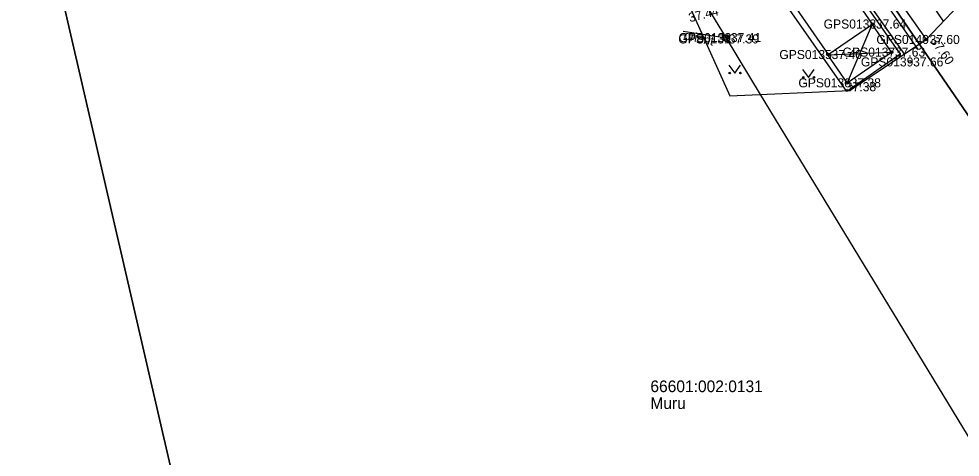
# Model space of a CAD drawing. Extents: x 626224 to 628280, y 6467750 to 6471135.
# Drawn here: x 627647 to 627719.8, y 6468553.4 to 6468587.3 of the extents above; entities that cross this region are included whole.
import ezdxf

# ---------------------------------------------------------------- set-up
doc = ezdxf.new("R2010")
doc.units = 0
for name, color, linetype in [('HALJASTUS', 7, 'Continuous'), ('HOONE', 7, 'Continuous'), ('HOONEDET', 7, 'Continuous'), ('KORGUS-EH2000', 7, 'Continuous'), ('MOOTKORG-EH2000', 7, 'Continuous'), ('MOOTMPUNKT', 7, 'Continuous'), ('MOOTNR', 7, 'Continuous'), ('MOOTPIIR', 7, 'Continuous'), ('MPKAABEL', 7, 'Continuous'), ('MPOHULIIN', 7, 'Continuous'), ('Muu rajatis Katusealune', 7, 'Continuous'), ('PIIR', 7, 'Continuous'), ('POST', 7, 'Continuous'), ('SITRASS', 7, 'Continuous')]:
    doc.layers.add(name, color=color, linetype=linetype)

msp = doc.modelspace()

# ---------------------------------------------------------------- linework, layer by layer
at = {"layer": 'HALJASTUS'}
for p, q in [((627701.907, 6468583.694), (627702.37, 6468583.087)), ((627702.37, 6468583.087), (627702.816, 6468583.694)), ((627707.596, 6468583.357), (627708.06, 6468582.75)), ((627708.06, 6468582.75), (627708.505, 6468583.357))]:
    msp.add_line(p, q, dxfattribs=at)
for points in [[(627673.61, 6468619.969), (627672.976, 6468621.286), (627679.187, 6468622.456), (627687.969, 6468624.157), (627689.948, 6468620.551), (627692.796, 6468621.064), (627698.292, 6468613.159), (627705.989, 6468601.538), (627717.166, 6468585.678)], [(627716.572, 6468584.873), (627705.028, 6468601.396), (627692.406, 6468620.356), (627689.621, 6468619.759), (627687.703, 6468623.543), (627673.321, 6468620.739)], [(627673.61, 6468619.969), (627679.701, 6468621.092), (627687.315, 6468622.642), (627689.297, 6468618.889), (627691.61, 6468619.392), (627696.609, 6468612.017), (627704.309, 6468600.39), (627715.503, 6468584.506)]]:
    msp.add_lwpolyline(points, dxfattribs=at)
for centre in [(627701.969, 6468583.087), (627702.798, 6468583.087), (627707.659, 6468582.75), (627708.488, 6468582.75)]:
    msp.add_circle(centre, 0.055, dxfattribs=at)
at = {"layer": 'HOONE'}
for p, q in [((627714.488, 6468584.702), (627713.001, 6468586.862)), ((627711.065, 6468582.328), (627709.57, 6468584.502)), ((627711.065, 6468582.328), (627714.488, 6468584.702))]:
    msp.add_line(p, q, dxfattribs=at)
msp.add_lwpolyline([(627706.037, 6468589.677), (627709.589, 6468584.515), (627713.017, 6468586.873), (627709.466, 6468592.035)], close=True, dxfattribs=at)
at = {"layer": 'HOONEDET'}
for p, q in [((627713.001, 6468586.862), (627711.065, 6468582.328)), ((627709.57, 6468584.502), (627714.488, 6468584.702))]:
    msp.add_line(p, q, dxfattribs=at)
at = {"layer": 'KORGUS-EH2000'}
for centre in [(627701.799, 6468585.823), (627717.166, 6468585.678), (627711.065, 6468582.328)]:
    msp.add_circle(centre, 0.1, dxfattribs=at)
at = {"layer": 'MOOTMPUNKT'}
for centre in [(627713.017, 6468586.873), (627701.634, 6468585.72), (627701.799, 6468585.823), (627717.166, 6468585.678), (627714.488, 6468584.702), (627709.588, 6468584.515), (627715.897, 6468583.946), (627711.065, 6468582.328)]:
    msp.add_circle(centre, 0.1, dxfattribs=at)
at = {"layer": 'MOOTPIIR'}
msp.add_lwpolyline([(627644.92, 6468614.927), (627687.389, 6468622.904), (627689.377, 6468619.311), (627692.038, 6468619.76), (627702.956, 6468602.021), (627695.606, 6468595.477), (627701.992, 6468581.333), (627711.232, 6468581.738), (627717.166, 6468585.678), (627720.646, 6468589.364)], dxfattribs=at)
at = {"layer": 'MPKAABEL'}
msp.add_line((627701.716, 6468585.772), (627698.369, 6468586.307), dxfattribs=at)
at = {"layer": 'MPOHULIIN'}
for points in [[(627704.355, 6468581.436), (627701.716, 6468585.772), (627695.728, 6468595.585)], [(627776.772, 6468462.547), (627753.896, 6468500.245), (627726.889, 6468544.419), (627704.355, 6468581.436)]]:
    msp.add_lwpolyline(points, dxfattribs=at)
at = {"layer": 'Muu rajatis Katusealune'}
msp.add_lwpolyline([(627705.521, 6468589.562), (627709.645, 6468592.435), (627715.151, 6468584.531), (627711.028, 6468581.659)], close=True, dxfattribs=at)
at = {"layer": 'PIIR'}
msp.add_lwpolyline([(627746.91, 6468541.23), (627688.18, 6468626.77), (627684.35, 6468632.16), (627686.69, 6468632.75), (627663.66, 6468662.2), (627667.34, 6468664.86), (627649.05, 6468692.73), (627646.31, 6468691.19), (627629.12, 6468721.76), (627618.92, 6468715.04), (627606.91, 6468724.16), (627579.16, 6468687.58), (627549.96, 6468707.41), (627588.77, 6468756.22), (627618.05, 6468733.86), (627619.84, 6468735.06), (627604.18, 6468764.29), (627579.83, 6468812.09), (627559.2, 6468856.67), (627547.01, 6468886.57), (627533.67, 6468925.79), (627531.86, 6468935.62), (627512.37, 6469002.4)], dxfattribs=at)
for points in [[(627746.91, 6468541.23), (627666.94, 6468517.08), (627653, 6468577.43), (627643.52, 6468618.24), (627688.18, 6468626.77)], [(627599.49, 6468616.8), (627643.52, 6468618.24), (627653, 6468577.43), (627666.94, 6468517.08), (627608.44, 6468499.25), (627602.15, 6468514.88), (627588.44, 6468509.87), (627563.73, 6468583.75), (627555.29, 6468612.05)]]:
    msp.add_lwpolyline(points, close=True, dxfattribs=at)
at = {"layer": 'POST'}
for radius in [0.25, 0.0234]:
    msp.add_circle((627701.716, 6468585.772), radius, dxfattribs=at)
at = {"layer": 'SITRASS'}
msp.add_lwpolyline([(627718.499, 6468587.089), (627713.907, 6468593.848), (627710.374, 6468599.048), (627699.564, 6468614.681), (627695.628, 6468619.665), (627689.767, 6468629.543), (627685.369, 6468635.281)], dxfattribs=at)

# ---------------------------------------------------------------- texts
at = {"layer": 'KORGUS-EH2000'}
for s, rotation, p in [(' 37.44', 13.88601, (627698.633, 6468586.945)), (' 37.60', 305.17261, (627717.309, 6468585.778))]:
    msp.add_text(s, height=0.7, rotation=rotation, dxfattribs=at).set_placement(p)
for s, p in [(' 37.41', (627701.799, 6468585.474)), (' 37.38', (627710.695, 6468581.678))]:
    msp.add_text(s, height=0.7, dxfattribs=at).set_placement(p)
at = {"layer": 'MOOTKORG-EH2000'}
for s, p in [(' 37.64', (627713.017, 6468586.523)), (' 37.41', (627701.799, 6468585.474)), (' 37.39', (627701.634, 6468585.37)), (' 37.60', (627717.166, 6468585.328)), (' 37.46', (627709.588, 6468584.165)), (' 37.63', (627714.488, 6468584.352)), (' 37.66', (627715.897, 6468583.596)), (' 37.38', (627711.065, 6468581.978))]:
    msp.add_text(s, height=0.7, dxfattribs=at).set_placement(p)
at = {"layer": 'MOOTNR'}
for s, p in [('GPS0138 ', (627709.237, 6468586.523)), ('GPS0132 ', (627698.02, 6468585.474)), ('GPS0131 ', (627697.994, 6468585.37)), ('GPS0140 ', (627713.316, 6468585.328)), ('GPS0135 ', (627705.809, 6468584.165)), ('GPS0137 ', (627710.708, 6468584.352)), ('GPS0139 ', (627712.117, 6468583.596)), ('GPS0136 ', (627707.285, 6468581.978))]:
    msp.add_text(s, height=0.7, dxfattribs=at).set_placement(p)
at = {"layer": 'MPKAABEL'}
msp.add_text('orient', height=0.7, rotation=347.92105, dxfattribs=at).set_placement((627698.368, 6468585.691))
at = {"layer": 'PIIR'}
for s, p in [('66601:002:0131', (627695.832, 6468558.43)), ('Muru', (627695.832, 6468557.13))]:
    msp.add_text(s, height=0.9, dxfattribs=at).set_placement(p)

doc.saveas('drawing.dxf')
